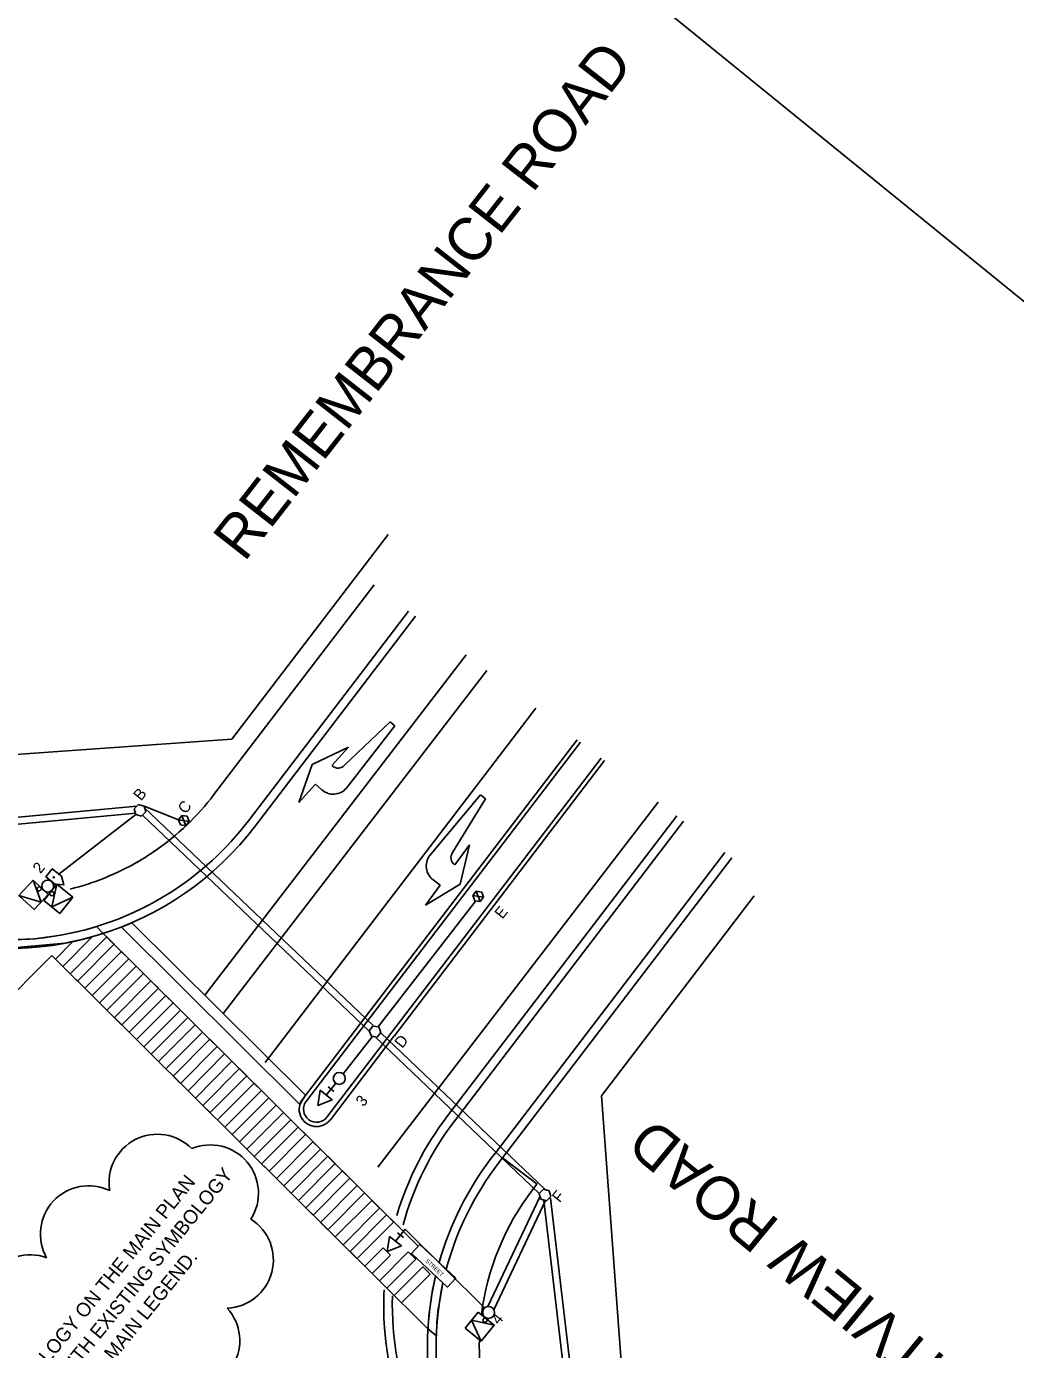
# Model space of a CAD drawing. Extents: x 592613 to 600223, y 4837996 to 4840103.
# Drawn here: x 592773.7 to 592830.8, y 4839026 to 4839102.5 of the extents above; entities that cross this region are included whole.
import ezdxf

# ---------------------------------------------------------------- set-up
doc = ezdxf.new("R2010")
doc.units = 0
for name, color, linetype in [('ENG_BORDER', 7, 'Continuous'), ('ENG_CURB-BACK', 7, 'Continuous'), ('ENG_EPAVT', 7, 'Continuous'), ('ENG_LANEWAY', 7, 'Continuous'), ('ENG_LIMITS', 7, 'Continuous'), ('ENG_SIDEWALK', 7, 'Continuous'), ('ENG_TX_TITLEBLOCK', 7, 'Continuous'), ('Level 12', 7, 'Continuous'), ('Level 32', 7, 'Continuous'), ('Level 33', 7, 'Continuous'), ('PMK_LANE', 7, 'Continuous'), ('ROW_ENG_ROW', 7, 'Continuous'), ('ROW_ENG_ROW BO', 7, 'Continuous'), ('TCS_100mm-NEW', 7, 'Continuous'), ('TCS_50mm-NEW', 7, 'Continuous'), ('TCS_75mm-NEW', 7, 'Continuous'), ('TCS_ELEC-CHAMBER-NEW', 7, 'Continuous'), ('TCS_LUMINAIRE-NEW', 7, 'Continuous'), ('TCS_POLE-NEW', 7, 'Continuous'), ('TCS_PUSHBUTTON', 7, 'Continuous'), ('TCS_RADAR', 7, 'Continuous'), ('TCS_SIGN', 7, 'Continuous'), ('TCS_SIGNALHEAD', 7, 'Continuous')]:
    doc.layers.add(name, color=color, linetype=linetype)

msp = doc.modelspace()

# ---------------------------------------------------------------- linework, layer by layer
at = {"layer": 'ENG_BORDER'}
msp.add_lwpolyline([(592762.862, 4838886.033), (592888.241, 4839040.345), (592783.858, 4839125.156)], dxfattribs=at)
at = {"layer": 'ENG_CURB-BACK'}
for p, q in [((592793.778, 4839070.184), (592784.516, 4839058.054)), ((592795.765, 4839068.667), (592786.503, 4839056.537)), ((592805.7, 4839061.082), (592793.918, 4839045.65)), ((592811.661, 4839056.53), (592798.414, 4839039.181)), ((592814.443, 4839054.406), (592801.196, 4839037.057)), ((592801.196, 4839037.057), (592800.943, 4839036.724))]:
    msp.add_line(p, q, dxfattribs=at)
for centre, start, end in [((592772.594, 4839067.157), 302.29593, 322.63771), ((592772.594, 4839067.157), 252.07774, 302.49821), ((592812.324, 4839028.561), 142.63771, 164.7037), ((592814.852, 4839026.104), 142.63771, 165.07872), ((592814.852, 4839026.104), 167.73061, 225.82889), ((592812.324, 4839028.561), 178.34066, 225.82889)]:
    msp.add_arc(centre, 17.5, start, end, dxfattribs=at)
at = {"layer": 'ENG_EPAVT'}
for p, q in [((592796.162, 4839068.364), (592786.901, 4839056.234)), ((592805.501, 4839061.233), (592793.769, 4839045.867)), ((592806.892, 4839060.171), (592794.788, 4839044.318)), ((592807.091, 4839060.02), (592794.945, 4839044.112)), ((592811.264, 4839056.834), (592798.017, 4839039.484)), ((592814.045, 4839054.71), (592800.799, 4839037.36)), ((592793.769, 4839045.867), (592789.664, 4839040.491)), ((592793.915, 4839045.646), (592789.832, 4839040.299)), ((592794.788, 4839044.318), (592791.041, 4839039.411)), ((592794.94, 4839044.106), (592791.241, 4839039.26)), ((592800.799, 4839037.36), (592800.545, 4839037.028))]:
    msp.add_line(p, q, dxfattribs=at)
for centre, radius, start, end in [((592772.594, 4839067.157), 18, 251.2988, 322.63771), ((592790.442, 4839039.863), 1, 141.10157, 322.94426), ((592790.442, 4839039.863), 0.75, 144.41151, 322.94426), ((592812.324, 4839028.561), 18, 142.63771, 163.31048), ((592814.852, 4839026.104), 18, 142.63771, 164.22726), ((592814.852, 4839026.104), 18, 166.78302, 225.82889), ((592812.324, 4839028.561), 18, 177.24575, 184.2333), ((592812.324, 4839028.561), 18, 184.2333, 225.82889)]:
    msp.add_arc(centre, radius, start, end, dxfattribs=at)
at = {"layer": 'ENG_LANEWAY'}
for p, q in [((592799.094, 4839066.146), (592783.981, 4839046.459)), ((592800.284, 4839065.232), (592785.07, 4839045.415)), ((592810.199, 4839057.62), (592793.99, 4839036.507))]:
    msp.add_line(p, q, dxfattribs=at)
at = {"layer": 'ENG_LIMITS'}
for points in [[(592778.119, 4839050.026), (592777.723, 4839050.427), (592777.481, 4839050.349), (592777.02, 4839050.224), (592775.671, 4839049.93), (592774.169, 4839049.721), (592773.084, 4839049.671), (592772.54, 4839049.646), (592771.553, 4839049.69), (592771.352, 4839049.2), (592771.895, 4839049.169), (592772.416, 4839049.159), (592772.909, 4839049.163), (592773.173, 4839049.165), (592773.631, 4839049.188), (592774.226, 4839049.233), (592774.825, 4839049.296), (592775.913, 4839049.465), (592772.454, 4839049.158), (592775.898, 4839049.463), (592776.144, 4839049.517), (592776.956, 4839049.693), (592777.648, 4839049.885)], [(592796.883, 4839027.16), (592797.381, 4839026.756), (592797.397, 4839027.549), (592797.479, 4839028.323), (592797.527, 4839028.575), (592797.655, 4839029.353), (592797.751, 4839029.823), (592797.329, 4839030.22), (592797.154, 4839029.421), (592797.046, 4839028.733), (592796.992, 4839028.342), (592796.951, 4839027.978)]]:
    msp.add_lwpolyline(points, close=True, dxfattribs=at)
for centre, radius, start, end in [((592781.242, 4839035.629), 2.793, 44.63697, 189.63697), ((592784.296, 4839035.012), 2.791, 327.47426, 112.47426), ((592777.274, 4839032.646), 2.793, 64.24042, 209.24042), ((592785.155, 4839031.152), 2.793, 272.64671, 57.64671), ((592773.893, 4839028.653), 2.793, 70.23304, 215.23304), ((592783.214, 4839026.487), 2.793, 257.17277, 42.17277)]:
    msp.add_arc(centre, radius, start, end, dxfattribs=at)
at = {"layer": 'ENG_SIDEWALK'}
for p, q in [((592803.195, 4839035.53), (592801.196, 4839037.057)), ((592802.786, 4839035.843), (592801.196, 4839037.057)), ((592802.93, 4839035.207), (592803.183, 4839035.539))]:
    msp.add_line(p, q, dxfattribs=at)
for centre, start, end in [((592772.594, 4839067.157), 304.59019, 322.63771), ((592772.594, 4839067.157), 299.79888, 305.49588), ((592772.594, 4839067.157), 283.88784, 300.15122), ((592814.852, 4839026.104), 142.63771, 172.78724), ((592814.852, 4839026.104), 178.35209, 199.44066)]:
    msp.add_arc(centre, 15, start, end, dxfattribs=at)
at = {"layer": 'Level 12'}
for p, q in [((592792.058, 4839059.754), (592794.705, 4839062.268)), ((592794.978, 4839062.024), (592792.156, 4839058.414)), ((592794.705, 4839062.268), (592794.978, 4839062.024)), ((592790.183, 4839059.796), (592792.285, 4839060.803)), ((592792.285, 4839060.803), (592791.33, 4839059.733)), ((592789.419, 4839057.593), (592790.183, 4839059.796)), ((592790.375, 4839058.664), (592789.419, 4839057.593)), ((592790.744, 4839058.334), (592790.375, 4839058.664)), ((592799.914, 4839058.036), (592796.976, 4839054.519)), ((592798.306, 4839054.704), (592800.209, 4839057.82)), ((592800.209, 4839057.82), (592799.914, 4839058.036)), ((592799.285, 4839055.147), (592798.439, 4839053.988)), ((592798.741, 4839052.88), (592799.285, 4839055.147)), ((592797.194, 4839053.122), (592797.594, 4839052.83)), ((592796.748, 4839051.671), (592798.741, 4839052.88)), ((592797.594, 4839052.83), (592796.748, 4839051.671))]:
    msp.add_line(p, q, dxfattribs=at)
for centre, radius, start, end in [((592791.685, 4839060.087), 0.5, 228.24691, 318.27059), ((592791.411, 4839059.08), 1, 228.24204, 318.26422), ((592798.71, 4839054.409), 0.5, 143.84426, 233.86795), ((592797.783, 4839053.93), 1, 143.85063, 233.87282)]:
    msp.add_arc(centre, radius, start, end, dxfattribs=at)
at = {"layer": 'PMK_LANE'}
for p, q in [((592803.117, 4839063.054), (592787.475, 4839042.568)), ((592779.163, 4839050.399), (592789.484, 4839040.148)), ((592779.764, 4839050.647), (592789.804, 4839040.675)), ((592776.353, 4839049.554), (592775.351, 4839048.547)), ((592775.777, 4839048.124), (592777.476, 4839049.832)), ((592778.319, 4839049.828), (592776.202, 4839047.701)), ((592776.628, 4839047.279), (592778.745, 4839049.405)), ((592778.119, 4839050.026), (592793.483, 4839034.765)), ((592778.745, 4839049.405), (592778.319, 4839049.828)), ((592775.139, 4839048.757), (592755.211, 4839028.681)), ((592775.139, 4839048.757), (592796.883, 4839027.16)), ((592775.351, 4839048.547), (592775.777, 4839048.124)), ((592779.17, 4839048.982), (592777.054, 4839046.856)), ((592777.48, 4839046.433), (592779.596, 4839048.559)), ((592779.596, 4839048.559), (592779.17, 4839048.982)), ((592780.022, 4839048.136), (592777.905, 4839046.01)), ((592780.447, 4839047.713), (592780.022, 4839048.136)), ((592776.202, 4839047.701), (592776.628, 4839047.279)), ((592778.331, 4839045.587), (592780.447, 4839047.713)), ((592780.873, 4839047.291), (592778.757, 4839045.164)), ((592781.299, 4839046.868), (592780.873, 4839047.291)), ((592777.054, 4839046.856), (592777.48, 4839046.433)), ((592779.182, 4839044.742), (592781.299, 4839046.868)), ((592781.724, 4839046.445), (592779.608, 4839044.319)), ((592782.15, 4839046.022), (592781.724, 4839046.445)), ((592777.905, 4839046.01), (592778.331, 4839045.587)), ((592780.034, 4839043.896), (592782.15, 4839046.022)), ((592782.576, 4839045.599), (592780.459, 4839043.473)), ((592783.002, 4839045.177), (592782.576, 4839045.599)), ((592778.757, 4839045.164), (592779.182, 4839044.742)), ((592780.885, 4839043.05), (592783.002, 4839045.177)), ((592783.427, 4839044.754), (592781.311, 4839042.627)), ((592783.853, 4839044.331), (592783.427, 4839044.754)), ((592779.608, 4839044.319), (592780.034, 4839043.896)), ((592781.736, 4839042.205), (592783.853, 4839044.331)), ((592780.459, 4839043.473), (592780.885, 4839043.05)), ((592784.279, 4839043.908), (592782.162, 4839041.782)), ((592782.588, 4839041.359), (592784.704, 4839043.485)), ((592784.704, 4839043.485), (592784.279, 4839043.908)), ((592781.311, 4839042.627), (592781.736, 4839042.205)), ((592785.13, 4839043.062), (592783.014, 4839040.936)), ((592783.439, 4839040.513), (592785.556, 4839042.64)), ((592785.556, 4839042.64), (592785.13, 4839043.062)), ((592782.162, 4839041.782), (592782.588, 4839041.359)), ((592785.981, 4839042.217), (592783.865, 4839040.09)), ((592784.291, 4839039.668), (592786.407, 4839041.794)), ((592786.407, 4839041.794), (592785.981, 4839042.217)), ((592783.014, 4839040.936), (592783.439, 4839040.513)), ((592786.833, 4839041.371), (592784.716, 4839039.245)), ((592785.142, 4839038.822), (592787.258, 4839040.948)), ((592787.258, 4839040.948), (592786.833, 4839041.371)), ((592787.684, 4839040.525), (592785.568, 4839038.399)), ((592785.993, 4839037.976), (592788.11, 4839040.103)), ((592788.11, 4839040.103), (592787.684, 4839040.525)), ((592783.865, 4839040.09), (592784.291, 4839039.668)), ((592788.536, 4839039.68), (592786.419, 4839037.553)), ((592788.961, 4839039.257), (592788.536, 4839039.68)), ((592784.716, 4839039.245), (592785.142, 4839038.822)), ((592786.845, 4839037.131), (592788.961, 4839039.257)), ((592789.387, 4839038.834), (592787.271, 4839036.708)), ((592789.813, 4839038.411), (592789.387, 4839038.834)), ((592785.568, 4839038.399), (592785.993, 4839037.976)), ((592787.696, 4839036.285), (592789.813, 4839038.411)), ((592790.238, 4839037.988), (592788.122, 4839035.862)), ((592790.664, 4839037.566), (592790.238, 4839037.988)), ((592786.419, 4839037.553), (592786.845, 4839037.131)), ((592788.548, 4839035.439), (592790.664, 4839037.566)), ((592791.09, 4839037.143), (592788.973, 4839035.017)), ((592791.515, 4839036.72), (592791.09, 4839037.143)), ((592787.271, 4839036.708), (592787.696, 4839036.285)), ((592789.399, 4839034.594), (592791.515, 4839036.72)), ((592791.941, 4839036.297), (592789.825, 4839034.171)), ((592792.367, 4839035.874), (592791.941, 4839036.297)), ((592788.122, 4839035.862), (592788.548, 4839035.439)), ((592790.25, 4839033.748), (592792.367, 4839035.874)), ((592788.973, 4839035.017), (592789.399, 4839034.594)), ((592792.792, 4839035.451), (592790.676, 4839033.325)), ((592791.102, 4839032.902), (592793.218, 4839035.029)), ((592793.218, 4839035.029), (592792.792, 4839035.451)), ((592793.483, 4839034.765), (592796.32, 4839031.948)), ((592789.825, 4839034.171), (592790.25, 4839033.748)), ((592793.634, 4839034.595), (592791.527, 4839032.48)), ((592791.983, 4839032.027), (592794.089, 4839034.143)), ((592794.089, 4839034.143), (592793.634, 4839034.595)), ((592790.676, 4839033.325), (592791.102, 4839032.902)), ((592794.495, 4839033.76), (592792.379, 4839031.634)), ((592792.785, 4839031.23), (592794.902, 4839033.357)), ((592794.902, 4839033.357), (592794.495, 4839033.76)), ((592791.527, 4839032.48), (592791.983, 4839032.027)), ((592794.288, 4839031.851), (592793.23, 4839030.788)), ((592794.714, 4839031.428), (592794.288, 4839031.851)), ((592792.379, 4839031.634), (592792.785, 4839031.23)), ((592793.656, 4839030.365), (592794.714, 4839031.428)), ((592795.748, 4839031.616), (592794.082, 4839029.943)), ((592794.508, 4839029.519), (592796.174, 4839031.193)), ((592796.174, 4839031.193), (592795.748, 4839031.616)), ((592793.23, 4839030.788), (592793.656, 4839030.365)), ((592796.586, 4839030.757), (592794.933, 4839029.097)), ((592795.359, 4839028.674), (592797.012, 4839030.334)), ((592797.012, 4839030.334), (592796.586, 4839030.757)), ((592794.082, 4839029.943), (592794.508, 4839029.519)), ((592794.933, 4839029.097), (592795.359, 4839028.674))]:
    msp.add_line(p, q, dxfattribs=at)
msp.add_lwpolyline([(592779.163, 4839050.399), (592779.764, 4839050.647), (592789.804, 4839040.675), (592789.484, 4839040.148)], close=True, dxfattribs=at)
msp.add_lwpolyline([(592777.218, 4839049.761), (592777.22, 4839049.753), (592776.936, 4839049.689)], dxfattribs=at)
for start, end in [(282.05527, 283.96019), (284.88737, 285.73894)]:
    msp.add_arc((592772.594, 4839067.157), 18, start, end, dxfattribs=at)
at = {"layer": 'ROW_ENG_ROW'}
for p, q in [((592765.752, 4839059.862), (592785.547, 4839061.253)), ((592808.565, 4839018.27), (592806.91, 4839040.637))]:
    msp.add_line(p, q, dxfattribs=at)
at = {"layer": 'ROW_ENG_ROW BO'}
for p, q in [((592785.547, 4839061.253), (592794.586, 4839073.092)), ((592806.91, 4839040.637), (592815.743, 4839052.206))]:
    msp.add_line(p, q, dxfattribs=at)
at = {"layer": 'TCS_100mm-NEW'}
for p, q in [((592780.049, 4839057.397), (592768.465, 4839056.313)), ((592793.709, 4839044.706), (592780.483, 4839057.31)), ((592793.659, 4839044.061), (592791.974, 4839041.915)), ((592803.67, 4839035.212), (592794.154, 4839044.281)), ((592800.353, 4839028.461), (592803.364, 4839034.83)), ((592806.039, 4839017.197), (592803.96, 4839034.723))]:
    msp.add_line(p, q, dxfattribs=at)
at = {"layer": 'TCS_50mm-NEW'}
for p, q in [((592779.993, 4839056.99), (592768.886, 4839055.951)), ((592782.465, 4839056.589), (592780.483, 4839057.388)), ((592793.499, 4839044.355), (592780.376, 4839056.86)), ((592793.995, 4839044.607), (592799.657, 4839051.906)), ((592803.319, 4839034.997), (592793.825, 4839044.044)), ((592800.701, 4839028.261), (592803.67, 4839034.589)), ((592805.589, 4839017.594), (592803.576, 4839034.561))]:
    msp.add_line(p, q, dxfattribs=at)
at = {"layer": 'TCS_75mm-NEW'}
msp.add_line((592779.995, 4839056.9), (592775.555, 4839053.464), dxfattribs=at)
at = {"layer": 'TCS_ELEC-CHAMBER-NEW'}
for p, q in [((592780.149, 4839057.478), (592779.905, 4839057.233)), ((592779.905, 4839057.233), (592779.995, 4839056.9)), ((592780.483, 4839057.388), (592780.149, 4839057.478)), ((592780.328, 4839056.81), (592780.573, 4839057.055)), ((592780.573, 4839057.055), (592780.483, 4839057.388)), ((592779.995, 4839056.9), (592780.328, 4839056.81)), ((592782.659, 4839056.854), (592782.458, 4839056.606)), ((592782.458, 4839056.606), (592783.088, 4839056.507)), ((592782.458, 4839056.606), (592782.573, 4839056.308)), ((592782.573, 4839056.308), (592782.888, 4839056.259)), ((592782.888, 4839056.259), (592782.659, 4839056.854)), ((592782.974, 4839056.804), (592782.659, 4839056.854)), ((592782.888, 4839056.259), (592783.088, 4839056.507)), ((592783.088, 4839056.507), (592782.974, 4839056.804)), ((592799.674, 4839052.467), (592799.473, 4839052.219)), ((592799.903, 4839051.872), (592799.674, 4839052.467)), ((592799.989, 4839052.417), (592799.674, 4839052.467)), ((592800.103, 4839052.12), (592799.989, 4839052.417)), ((592799.473, 4839052.219), (592800.103, 4839052.12)), ((592799.473, 4839052.219), (592799.588, 4839051.921)), ((592799.588, 4839051.921), (592799.903, 4839051.872)), ((592799.903, 4839051.872), (592800.103, 4839052.12)), ((592793.693, 4839044.675), (592793.483, 4839044.401)), ((592793.483, 4839044.401), (592793.615, 4839044.081)), ((592793.615, 4839044.081), (592793.957, 4839044.036)), ((592794.036, 4839044.629), (592793.693, 4839044.675)), ((592793.957, 4839044.036), (592794.168, 4839044.31)), ((592794.168, 4839044.31), (592794.036, 4839044.629)), ((592803.564, 4839035.242), (592803.319, 4839034.997)), ((592803.319, 4839034.997), (592803.409, 4839034.664)), ((592803.898, 4839035.152), (592803.564, 4839035.242)), ((592803.743, 4839034.574), (592803.987, 4839034.819)), ((592803.987, 4839034.819), (592803.898, 4839035.152)), ((592803.409, 4839034.664), (592803.743, 4839034.574))]:
    msp.add_line(p, q, dxfattribs=at)
at = {"layer": 'TCS_LUMINAIRE-NEW'}
msp.add_line((592795.568, 4839032.924), (592800.158, 4839028.376), dxfattribs=at)
at = {"layer": 'TCS_POLE-NEW'}
for centre in [(592774.904, 4839052.768), (592791.76, 4839041.644), (592800.387, 4839028.117)]:
    msp.add_circle(centre, 0.346, dxfattribs=at)
at = {"layer": 'TCS_PUSHBUTTON'}
for centre in [(592774.411, 4839052.608), (592775.147, 4839052.33), (592800.178, 4839027.666)]:
    msp.add_circle(centre, 0.12, dxfattribs=at)
at = {"layer": 'TCS_RADAR'}
msp.add_lwpolyline([(592774.792, 4839053.312), (592775.167, 4839053.772), (592775.709, 4839053.332), (592775.839, 4839052.833), (592775.334, 4839052.871)], close=True, dxfattribs=at)
msp.add_circle((592775.253, 4839053.276), 0.0323, dxfattribs=at)
at = {"layer": 'TCS_SIGN'}
msp.add_lwpolyline([(592796.412, 4839032.046), (592798.487, 4839030.1), (592798.005, 4839029.586), (592795.93, 4839031.532)], close=True, dxfattribs=at)
at = {"layer": 'TCS_SIGNALHEAD'}
for p, q in [((592774.934, 4839052.284), (592774.057, 4839053.104)), ((592775.431, 4839052.872), (592774.677, 4839051.939)), ((592773.238, 4839052.227), (592774.115, 4839051.408)), ((592774.115, 4839051.408), (592774.934, 4839052.284)), ((592774.677, 4839051.939), (592775.61, 4839051.185)), ((592775.61, 4839051.185), (592776.364, 4839052.118)), ((592790.519, 4839040.091), (592790.659, 4839040.963)), ((592790.659, 4839040.963), (592791.343, 4839040.406)), ((592791.001, 4839040.684), (592791.558, 4839041.369)), ((592791.28, 4839041.026), (592791.109, 4839041.166)), ((592791.28, 4839041.026), (592791.451, 4839040.887)), ((592791.343, 4839040.406), (592790.519, 4839040.091)), ((592794.529, 4839031.645), (592794.669, 4839032.517)), ((592794.669, 4839032.517), (592795.353, 4839031.96)), ((592795.012, 4839032.238), (592795.569, 4839032.923)), ((592795.29, 4839032.58), (592795.119, 4839032.72)), ((592795.29, 4839032.58), (592795.461, 4839032.441)), ((592795.353, 4839031.96), (592794.529, 4839031.645)), ((592799.786, 4839028.136), (592799.032, 4839027.203)), ((592800.72, 4839027.382), (592799.786, 4839028.136)), ((592799.032, 4839027.203), (592799.966, 4839026.449))]:
    msp.add_line(p, q, dxfattribs=at)
for points in [[(592774.057, 4839053.104), (592773.238, 4839052.227), (592774.524, 4839051.846), (592774.524, 4839051.846)], [(592776.364, 4839052.118), (592775.431, 4839052.872), (592775.143, 4839051.562), (592775.143, 4839051.562)], [(592790.659, 4839040.963), (592791.343, 4839040.406), (592790.519, 4839040.091), (592790.519, 4839040.091)], [(592794.669, 4839032.517), (592795.353, 4839031.96), (592794.529, 4839031.645), (592794.529, 4839031.645)], [(592799.966, 4839026.449), (592800.72, 4839027.382), (592799.409, 4839027.67), (592799.409, 4839027.67)]]:
    msp.add_lwpolyline(points, close=True, dxfattribs=at)

# ---------------------------------------------------------------- texts
at = {"layer": 'ENG_TX_TITLEBLOCK'}
for s, p in [('IS TO BE REPLACED WITH EXISTING SYMBOLOGY ', (592769.012, 4839015.586)), ('ALL DESIGN SYMBOLOGY ON THE MAIN PLAN', (592768.256, 4839016.906)), ('AS SHOWN IN THE MAIN LEGEND.', (592772.376, 4839017.477))]:
    msp.add_text(s, height=0.81055, rotation=50.90123, dxfattribs=at).set_placement(p)
at = {"layer": 'Level 32'}
msp.add_text('CREDITVIEW ROAD', height=2.5, rotation=140.5921, dxfattribs=at).set_placement((592834.239, 4839019.43))
at = {"layer": 'Level 33'}
msp.add_text('REMEMBRANCE ROAD', height=2.4783, rotation=52.00703, dxfattribs=at).set_placement((592786.266, 4839071.457))
at = {"layer": 'TCS_ELEC-CHAMBER-NEW'}
for s, p in [('B', (592780.3, 4839057.656)), ('C', (592782.869, 4839056.894)), ('E', (592801.181, 4839050.823)), ('D', (592795.396, 4839043.349)), ('F', (592804.5, 4839034.422))]:
    msp.add_text(s, height=0.65, rotation=51.05743, dxfattribs=at).set_placement(p)
at = {"layer": 'TCS_POLE-NEW'}
for s, p in [('2', (592774.483, 4839053.447)), ('3', (592793.152, 4839039.968)), ('4', (592800.981, 4839027.361))]:
    msp.add_text(s, height=0.65, rotation=51.05743, dxfattribs=at).set_placement(p)
at = {"layer": 'TCS_SIGN'}
msp.add_text('STREET', height=0.2407, rotation=316.83813, dxfattribs=at).set_placement((592796.709, 4839031.063))

doc.saveas('drawing.dxf')
